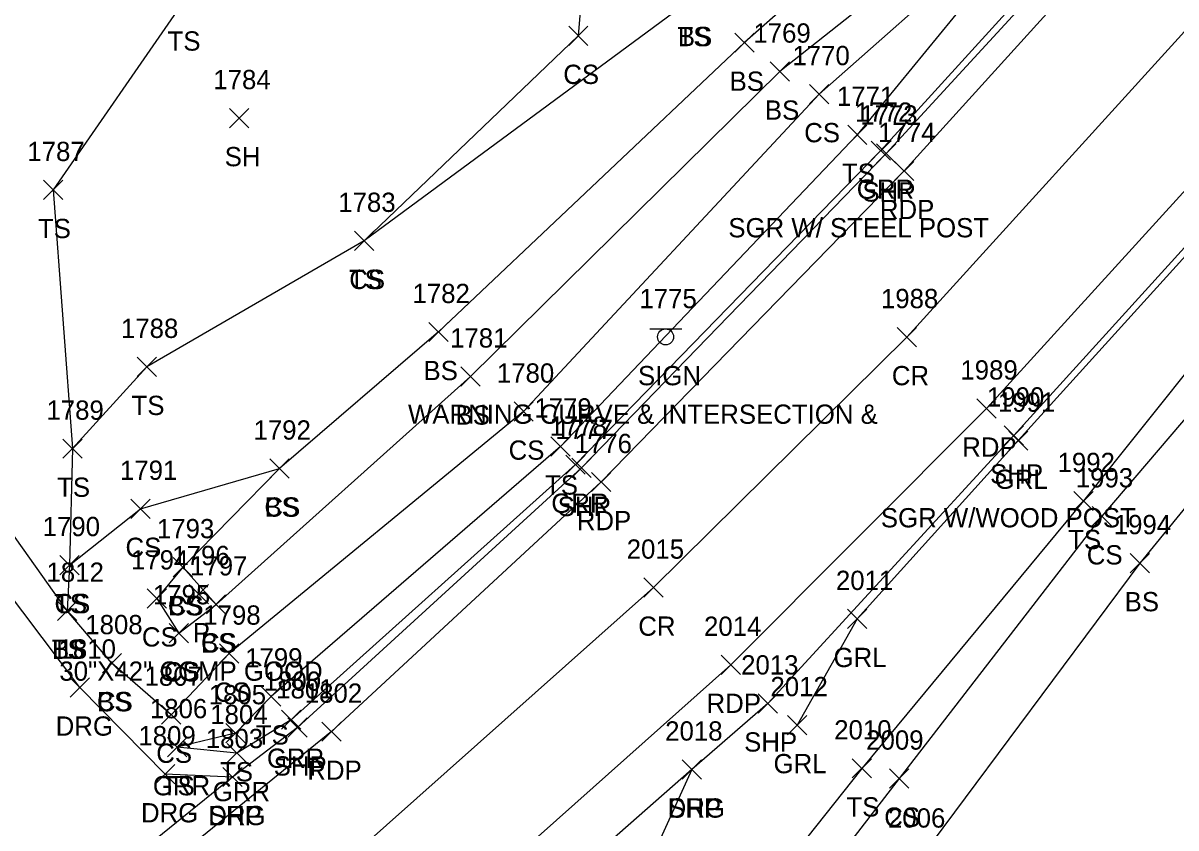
# Model space of a CAD drawing. Extents: x 1520648 to 1523413, y 732854 to 735518.
# Drawn here: x 1522132.5 to 1522252.1, y 733878.1 to 733961.6 of the extents above; entities that cross this region are included whole.
import ezdxf

# ---------------------------------------------------------------- set-up
doc = ezdxf.new("R2010")
doc.units = 0
for name, color, linetype in [('D_A', 7, 'Continuous'), ('D_C', 7, 'Continuous'), ('D_I', 7, 'Continuous'), ('D_TIC', 7, 'Continuous'), ('L_A', 7, 'Continuous'), ('L_I', 7, 'Continuous'), ('L_TIC', 7, 'Continuous'), ('LELB', 7, 'Continuous'), ('P_A', 7, 'Continuous'), ('P_I', 7, 'Continuous'), ('P_TIC', 7, 'Continuous'), ('PET', 7, 'Continuous'), ('PRC', 7, 'Continuous'), ('PSP', 7, 'Continuous'), ('R_A', 7, 'Continuous'), ('R_C', 7, 'Continuous'), ('R_I', 7, 'Continuous'), ('R_TIC', 7, 'Continuous'), ('RDG', 7, 'Continuous'), ('RGR', 7, 'Continuous'), ('S_A', 7, 'Continuous'), ('S_C', 7, 'Continuous'), ('S_I', 7, 'Continuous'), ('SSGN', 7, 'Continuous')]:
    doc.layers.add(name, color=color, linetype=linetype)

msp = doc.modelspace()

# ---------------------------------------------------------------- linework, layer by layer
at = {"layer": 'D_TIC'}
for points in [[(1522149.76, 733901.33), (1522151.76, 733903.33)], [(1522151.76, 733901.33), (1522149.76, 733903.33)]]:
    msp.add_lwpolyline(points, dxfattribs=at)
at = {"layer": 'L_TIC'}
for points in [[(1522189.12, 733959.27), (1522191.12, 733961.27)], [(1522191.12, 733959.27), (1522189.12, 733961.27)], [(1522206.37, 733958.56), (1522208.37, 733960.56)], [(1522208.37, 733958.56), (1522206.37, 733960.56)], [(1522206.37, 733958.56), (1522208.37, 733960.56)], [(1522208.37, 733958.56), (1522206.37, 733960.56)], [(1522210.03, 733955.56), (1522212.03, 733957.56)], [(1522212.03, 733955.56), (1522210.03, 733957.56)], [(1522214.11, 733953.22), (1522216.11, 733955.22)], [(1522216.11, 733953.22), (1522214.11, 733955.22)], [(1522153.95, 733950.73), (1522155.95, 733952.73)], [(1522155.95, 733950.73), (1522153.95, 733952.73)], [(1522218.06, 733949), (1522220.06, 733951)], [(1522220.06, 733949), (1522218.06, 733951)], [(1522134.66, 733943.27), (1522136.66, 733945.27)], [(1522136.66, 733943.27), (1522134.66, 733945.27)], [(1522166.92, 733937.99), (1522168.92, 733939.99)], [(1522168.92, 733937.99), (1522166.92, 733939.99)], [(1522166.92, 733937.99), (1522168.92, 733939.99)], [(1522168.92, 733937.99), (1522166.92, 733939.99)], [(1522174.61, 733928.53), (1522176.61, 733930.53)], [(1522176.61, 733928.53), (1522174.61, 733930.53)], [(1522144.37, 733924.91), (1522146.37, 733926.91)], [(1522146.37, 733924.91), (1522144.37, 733926.91)], [(1522177.95, 733923.91), (1522179.95, 733925.91)], [(1522179.95, 733923.91), (1522177.95, 733925.91)], [(1522183.45, 733920.27), (1522185.45, 733922.27)], [(1522185.45, 733920.27), (1522183.45, 733922.27)], [(1522136.65, 733916.42), (1522138.65, 733918.42)], [(1522138.65, 733916.42), (1522136.65, 733918.42)], [(1522136.65, 733916.42), (1522138.65, 733918.42)], [(1522138.65, 733916.42), (1522136.65, 733918.42)], [(1522187.26, 733916.65), (1522189.26, 733918.65)], [(1522189.26, 733916.65), (1522187.26, 733918.65)], [(1522158.12, 733914.36), (1522160.12, 733916.36)], [(1522160.12, 733914.36), (1522158.12, 733916.36)], [(1522158.12, 733914.36), (1522160.12, 733916.36)], [(1522160.12, 733914.36), (1522158.12, 733916.36)], [(1522143.71, 733910.18), (1522145.71, 733912.18)], [(1522145.71, 733910.18), (1522143.71, 733912.18)], [(1522241.52, 733910.99), (1522243.52, 733912.99)], [(1522243.52, 733910.99), (1522241.52, 733912.99)], [(1522243.42, 733909.4), (1522245.42, 733911.4)], [(1522245.42, 733909.4), (1522243.42, 733911.4)], [(1522136.34, 733904.34), (1522138.34, 733906.34)], [(1522138.34, 733904.34), (1522136.34, 733906.34)], [(1522136.34, 733904.34), (1522138.34, 733906.34)], [(1522138.34, 733904.34), (1522136.34, 733906.34)], [(1522148.1, 733904.12), (1522150.1, 733906.12)], [(1522150.1, 733904.12), (1522148.1, 733906.12)], [(1522148.1, 733904.12), (1522150.1, 733906.12)], [(1522150.1, 733904.12), (1522148.1, 733906.12)], [(1522247.35, 733904.54), (1522249.35, 733906.54)], [(1522249.35, 733904.54), (1522247.35, 733906.54)], [(1522145.41, 733900.88), (1522147.41, 733902.88)], [(1522147.41, 733900.88), (1522145.41, 733902.88)], [(1522136.09, 733899.6), (1522138.09, 733901.6)], [(1522138.09, 733899.6), (1522136.09, 733901.6)], [(1522136.09, 733899.6), (1522138.09, 733901.6)], [(1522138.09, 733899.6), (1522136.09, 733901.6)], [(1522151.54, 733900.26), (1522153.54, 733902.26)], [(1522153.54, 733900.26), (1522151.54, 733902.26)], [(1522151.54, 733900.26), (1522153.54, 733902.26)], [(1522153.54, 733900.26), (1522151.54, 733902.26)], [(1522151.54, 733900.26), (1522153.54, 733902.26)], [(1522153.54, 733900.26), (1522151.54, 733902.26)], [(1522147.69, 733897.26), (1522149.69, 733899.26)], [(1522149.69, 733897.26), (1522147.69, 733899.26)], [(1522152.91, 733895.15), (1522154.91, 733897.15)], [(1522154.91, 733895.15), (1522152.91, 733897.15)], [(1522140.75, 733894.16), (1522142.75, 733896.16)], [(1522142.75, 733894.16), (1522140.75, 733896.16)], [(1522140.75, 733894.16), (1522142.75, 733896.16)], [(1522142.75, 733894.16), (1522140.75, 733896.16)], [(1522157.26, 733890.71), (1522159.26, 733892.71)], [(1522159.26, 733890.71), (1522157.26, 733892.71)], [(1522146.9, 733888.81), (1522148.9, 733890.81)], [(1522148.9, 733888.81), (1522146.9, 733890.81)], [(1522153.55, 733886.89), (1522155.55, 733888.89)], [(1522155.55, 733886.89), (1522153.55, 733888.89)], [(1522147.5, 733885.44), (1522149.5, 733887.44)], [(1522149.5, 733885.44), (1522147.5, 733887.44)], [(1522218.52, 733883.24), (1522220.52, 733885.24)], [(1522220.52, 733883.24), (1522218.52, 733885.24)], [(1522222.41, 733882.18), (1522224.41, 733884.18)], [(1522224.41, 733882.18), (1522222.41, 733884.18)]]:
    msp.add_lwpolyline(points, dxfattribs=at)
at = {"layer": 'LELB'}
for points in [[(1522353.25, 734140.58), (1522319.92, 734106.37), (1522293, 734074.6), (1522275.62, 734051.29), (1522244.54, 734005.97), (1522222.7, 733979.34), (1522202, 733964.19), (1522167.92, 733938.99), (1522145.37, 733925.91), (1522137.65, 733917.42), (1522137.34, 733905.34), (1522137.09, 733900.6)], [(1522125.27, 734093.2), (1522135, 734067.14), (1522161.7, 734052.21), (1522168.2, 734018.04), (1522192.75, 733992.38), (1522190.12, 733960.27), (1522167.92, 733938.99)], [(1522105.42, 734074.14), (1522121.13, 734053.03), (1522134.54, 734027.27), (1522145.23, 734006.79), (1522143.45, 733990.96), (1522149.1, 733963.73), (1522135.66, 733944.27), (1522137.65, 733917.42)], [(1522234.99, 733978.89), (1522233.89, 733977.86), (1522225.33, 733975.44), (1522207.37, 733959.56)], [(1522239.33, 733974.37), (1522231.93, 733969.12), (1522215.11, 733954.22), (1522184.45, 733921.27), (1522153.91, 733896.15), (1522147.9, 733889.81), (1522141.75, 733895.16)], [(1522237.77, 733974.95), (1522230.05, 733971.66), (1522211.03, 733956.56), (1522178.95, 733924.91), (1522152.54, 733901.26)], [(1522241.57, 733972.22), (1522233.22, 733967.32), (1522219.06, 733950), (1522188.26, 733917.65), (1522158.26, 733891.71), (1522154.55, 733887.89), (1522148.5, 733886.44)], [(1522207.37, 733959.56), (1522175.61, 733929.53), (1522159.12, 733915.36), (1522149.1, 733905.12), (1522152.54, 733901.26)], [(1522141.75, 733895.16), (1522137.09, 733900.6), (1522127.81, 733913.65), (1522115.39, 733932.29), (1522101.35, 733953.08)], [(1522273.3, 733946.59), (1522271.43, 733944.22), (1522268.56, 733937.8), (1522262.2, 733922.49), (1522248.35, 733905.54), (1522225.71, 733875.09), (1522211.03, 733857.35), (1522192.48, 733835.82), (1522170.81, 733810.34), (1522151.93, 733786.41), (1522130.42, 733759.83), (1522111.64, 733741.03), (1522100.77, 733725.2)], [(1522266.63, 733945.22), (1522267.06, 733939.56), (1522257.32, 733925.54), (1522244.42, 733910.4), (1522223.41, 733883.18), (1522189.15, 733838.76), (1522168.77, 733813.86), (1522150.13, 733789.06), (1522128.4, 733762.92), (1522110.49, 733741.99), (1522098.34, 733726.66), (1522093.01, 733716.82)], [(1522270.74, 733944.98), (1522266.63, 733945.22), (1522254.91, 733927.51), (1522242.52, 733911.99), (1522219.52, 733884.24), (1522186.7, 733842.89), (1522166.07, 733817.07), (1522164.2, 733814.35), (1522137.24, 733813.36), (1522122.6, 733811.13)], [(1522137.34, 733905.34), (1522144.71, 733911.18), (1522159.12, 733915.36)], [(1522149.1, 733905.12), (1522146.41, 733901.88), (1522148.69, 733898.26), (1522152.54, 733901.26)]]:
    msp.add_lwpolyline(points, dxfattribs=at)
at = {"layer": 'P_TIC'}
for points in [[(1522221.05, 733947.06), (1522223.05, 733949.06)], [(1522223.05, 733947.06), (1522221.05, 733949.06)], [(1522222.91, 733945.24), (1522224.91, 733947.24)], [(1522224.91, 733945.24), (1522222.91, 733947.24)], [(1522223.2, 733928), (1522225.2, 733930)], [(1522225.2, 733928), (1522223.2, 733930)], [(1522231.46, 733920.59), (1522233.46, 733922.59)], [(1522233.46, 733920.59), (1522231.46, 733922.59)], [(1522234.29, 733917.79), (1522236.29, 733919.79)], [(1522236.29, 733917.79), (1522234.29, 733919.79)], [(1522189.45, 733914.42), (1522191.45, 733916.42)], [(1522191.45, 733914.42), (1522189.45, 733916.42)], [(1522191.48, 733912.96), (1522193.48, 733914.96)], [(1522193.48, 733912.96), (1522191.48, 733914.96)], [(1522196.91, 733902), (1522198.91, 733904)], [(1522198.91, 733902), (1522196.91, 733904)], [(1522204.93, 733893.99), (1522206.93, 733895.99)], [(1522206.93, 733893.99), (1522204.93, 733895.99)], [(1522208.78, 733889.98), (1522210.78, 733891.98)], [(1522210.78, 733889.98), (1522208.78, 733891.98)], [(1522159.99, 733887.49), (1522161.99, 733889.49)], [(1522161.99, 733887.49), (1522159.99, 733889.49)], [(1522163.52, 733887.05), (1522165.52, 733889.05)], [(1522165.52, 733887.05), (1522163.52, 733889.05)], [(1522200.9, 733883.12), (1522202.9, 733885.12)], [(1522202.9, 733883.12), (1522200.9, 733885.12)], [(1522153.25, 733882.34), (1522155.25, 733884.34)], [(1522155.25, 733882.34), (1522153.25, 733884.34)]]:
    msp.add_lwpolyline(points, dxfattribs=at)
at = {"layer": 'PET'}
for points in [[(1522409.89, 734185.46), (1522384.8, 734151.86), (1522362.15, 734120.96), (1522340.09, 734090.38), (1522317.27, 734060.02), (1522297.22, 734033.87), (1522262.69, 733990.17), (1522247.44, 733972.23), (1522223.91, 733946.24), (1522192.48, 733913.96), (1522164.52, 733888.05), (1522124.7, 733855.72), (1522089.98, 733831.33), (1522050.33, 733806.1), (1522008.23, 733782.16), (1521961.73, 733759.37), (1521937.85, 733748.92), (1521892.74, 733731.02), (1521853.04, 733716.93), (1521810.12, 733704.13), (1521784.9, 733696.8), (1521738.04, 733684.33), (1521683.5, 733669.74)], [(1522293.19, 733992.18), (1522263.71, 733955.95), (1522232.46, 733921.59), (1522205.93, 733894.99), (1522171.68, 733864.45), (1522150.76, 733846.95), (1522111.89, 733818.73), (1522077.26, 733795.56), (1522046.35, 733777.35), (1522014.71, 733760.04), (1521992.39, 733748.52), (1521963.75, 733735.05), (1521947.25, 733727.94), (1521903.49, 733710.07), (1521845.39, 733690.65), (1521824.85, 733681.25), (1521803.81, 733674.87), (1521790.98, 733674.84), (1521764.05, 733667.92), (1521729.46, 733658.42), (1521691.16, 733648.14)]]:
    msp.add_lwpolyline(points, dxfattribs=at)
at = {"layer": 'PRC'}
msp.add_lwpolyline([(1522254.71, 733962.62), (1522224.2, 733929), (1522197.91, 733903), (1522164.25, 733873.02), (1522142.54, 733855.17), (1522104.41, 733827.43), (1522070.85, 733804.7), (1522039.57, 733786.25), (1522009.6, 733770.04), (1521986.99, 733758.56), (1521958.12, 733745.43), (1521942.23, 733738.37), (1521896.32, 733720.33), (1521857.71, 733706.32), (1521841.62, 733701.43), (1521812.17, 733692.84), (1521787.03, 733685.66), (1521768.25, 733680.62), (1521726.09, 733669.37), (1521688.17, 733658.56)], dxfattribs=at)
at = {"layer": 'PSP'}
for points in [[(1522407.44, 734186.96), (1522382.7, 734153.4), (1522359.98, 734122.45), (1522337.92, 734092.02), (1522315.01, 734061.41), (1522295.21, 734035.76), (1522260.62, 733991.79), (1522245.88, 733973.99), (1522222.05, 733948.06), (1522190.45, 733915.42), (1522160.99, 733888.49), (1522154.25, 733883.34), (1522127.34, 733861.55), (1522088.3, 733833.58), (1522048.98, 733808.78), (1522007.27, 733785.06), (1521960.9, 733762.47), (1521936.68, 733751.08), (1521891.96, 733733.48), (1521851.86, 733719.56), (1521809.02, 733706.62), (1521784.1, 733699.99), (1521736.06, 733688.52), (1521682.58, 733672.91)], [(1522408.2, 734139.28), (1522381.04, 734102.47), (1522353.02, 734064.87), (1522324.01, 734025.28), (1522296.17, 733989.55), (1522266.63, 733953.31), (1522235.29, 733918.79), (1522209.78, 733890.98), (1522201.9, 733884.12), (1522173.49, 733859.11), (1522154.03, 733843.41), (1522113.55, 733816.07), (1522079.34, 733793.19), (1522048.3, 733774.46), (1522016.59, 733757.42), (1521993.94, 733745.83), (1521965.16, 733732.44), (1521948.66, 733724.97), (1521904.28, 733707.61), (1521888.63, 733701.99), (1521847.29, 733686.72), (1521809.29, 733673.67)]]:
    msp.add_lwpolyline(points, dxfattribs=at)
at = {"layer": 'R_TIC'}
for points in [[(1522220.51, 733947.35), (1522222.51, 733949.35)], [(1522222.51, 733947.35), (1522220.51, 733949.35)], [(1522234.76, 733917.25), (1522236.76, 733919.25)], [(1522236.76, 733917.25), (1522234.76, 733919.25)], [(1522188.83, 733914.76), (1522190.83, 733916.76)], [(1522190.83, 733914.76), (1522188.83, 733916.76)], [(1522218.05, 733898.75), (1522220.05, 733900.75)], [(1522220.05, 733898.75), (1522218.05, 733900.75)], [(1522137.42, 733891.63), (1522139.42, 733893.63)], [(1522139.42, 733891.63), (1522137.42, 733893.63)], [(1522159.34, 733888.29), (1522161.34, 733890.29)], [(1522161.34, 733888.29), (1522159.34, 733890.29)], [(1522211.83, 733887.73), (1522213.83, 733889.73)], [(1522213.83, 733887.73), (1522211.83, 733889.73)], [(1522147.5, 733885.44), (1522149.5, 733887.44)], [(1522149.5, 733885.44), (1522147.5, 733887.44)], [(1522153.71, 733884.83), (1522155.71, 733886.83)], [(1522155.71, 733884.83), (1522153.71, 733886.83)], [(1522146.27, 733882.63), (1522148.27, 733884.63)], [(1522148.27, 733882.63), (1522146.27, 733884.63)], [(1522200.9, 733883.12), (1522202.9, 733885.12)], [(1522202.9, 733883.12), (1522200.9, 733885.12)], [(1522153.25, 733882.34), (1522155.25, 733884.34)], [(1522155.25, 733882.34), (1522153.25, 733884.34)]]:
    msp.add_lwpolyline(points, dxfattribs=at)
at = {"layer": 'RDG'}
for points in [[(1522154.25, 733883.34), (1522147.27, 733883.63), (1522138.42, 733892.63), (1522124.65, 733910.85), (1522111.52, 733931.27), (1522101.35, 733953.08), (1522088.31, 733979.36), (1522086.25, 733984.71)], [(1522201.9, 733884.12), (1522195.75, 733870.56), (1522182.51, 733850.34), (1522162.18, 733834.79), (1522133.75, 733820.11), (1522113.55, 733816.07)]]:
    msp.add_lwpolyline(points, dxfattribs=at)
at = {"layer": 'RGR'}
for points in [[(1522309.58, 734064.85), (1522305.06, 734052.2), (1522294.68, 734036.56), (1522260.13, 733992.38), (1522248.03, 733977.91), (1522242.5, 733971.47), (1522221.51, 733948.35), (1522189.83, 733915.76), (1522160.34, 733889.29), (1522154.71, 733885.83), (1522148.5, 733886.44)], [(1522327.77, 734020.69), (1522316.41, 734013), (1522308.3, 734003.69), (1522296.64, 733988.96), (1522267.17, 733952.95), (1522235.76, 733918.25), (1522219.05, 733899.75), (1522212.83, 733888.73)]]:
    msp.add_lwpolyline(points, dxfattribs=at)
at = {"layer": 'SSGN'}
for p, q in [((1522197.53, 733929.86), (1522200.86, 733929.86)), ((1522199.17, 733929.02), (1522199.17, 733929.02))]:
    msp.add_line(p, q, dxfattribs=at)
msp.add_circle((1522199.17, 733929.02), 0.833, dxfattribs=at)

# ---------------------------------------------------------------- texts
at = {"layer": 'D_A'}
msp.add_text('P', height=2, dxfattribs=at).set_placement((1522150.13, 733897.33))
at = {"layer": 'D_C'}
msp.add_text('30"X42" CGMP GOOD', height=2, dxfattribs=at).set_placement((1522136.29, 733893.33))
at = {"layer": 'D_I'}
msp.add_text('1796', height=2, dxfattribs=at).set_placement((1522148.01, 733905.33))
at = {"layer": 'L_A'}
for s, p in [('TS', (1522200.41, 733959.19)), ('TS', (1522200.41, 733959.19)), ('BS', (1522200.44, 733959.19)), ('TS', (1522147.51, 733958.73)), ('CS', (1522188.56, 733955.27)), ('BS', (1522205.81, 733954.56)), ('BS', (1522205.81, 733954.56)), ('BS', (1522209.47, 733951.56)), ('CS', (1522213.55, 733949.22)), ('SH', (1522153.44, 733946.73)), ('TS', (1522217.47, 733945)), ('TS', (1522134.07, 733939.27)), ('TS', (1522166.33, 733933.99)), ('CS', (1522166.36, 733933.99)), ('BS', (1522174.06, 733924.53)), ('TS', (1522143.78, 733920.91)), ('BS', (1522177.39, 733919.91)), ('CS', (1522182.89, 733916.27)), ('TS', (1522136.06, 733912.42)), ('TS', (1522136.06, 733912.42)), ('TS', (1522186.67, 733912.65)), ('CS', (1522157.56, 733910.36)), ('BS', (1522157.56, 733910.36)), ('TS', (1522240.93, 733906.99)), ('CS', (1522143.15, 733906.18)), ('CS', (1522242.86, 733905.4)), ('BS', (1522246.79, 733900.54)), ('TS', (1522135.75, 733900.34)), ('CS', (1522135.78, 733900.34)), ('CS', (1522147.54, 733900.12)), ('BS', (1522147.54, 733900.12)), ('CS', (1522144.85, 733896.88)), ('CS', (1522150.98, 733896.26)), ('BS', (1522150.98, 733896.26)), ('BS', (1522150.98, 733896.26)), ('TS', (1522135.5, 733895.6)), ('BS', (1522135.53, 733895.6)), ('CS', (1522147.13, 733893.26)), ('CS', (1522152.35, 733891.15)), ('CS', (1522140.19, 733890.16)), ('BS', (1522140.19, 733890.16)), ('TS', (1522156.67, 733886.71)), ('CS', (1522146.34, 733884.81)), ('TS', (1522152.96, 733882.89)), ('TS', (1522146.91, 733881.44)), ('TS', (1522217.93, 733879.24)), ('CS', (1522221.85, 733878.18))]:
    msp.add_text(s, height=2, dxfattribs=at).set_placement(p)
at = {"layer": 'L_I'}
for s, p in [('1769', (1522208.28, 733959.56)), ('1770', (1522212.33, 733957.22)), ('1784', (1522152.26, 733954.73)), ('1771', (1522216.94, 733953)), ('1787', (1522132.97, 733947.27)), ('1783', (1522165.22, 733941.99)), ('1783', (1522165.22, 733941.99)), ('1782', (1522172.92, 733932.53)), ('1788', (1522142.68, 733928.91)), ('1781', (1522176.82, 733927.91)), ('1780', (1522181.67, 733924.27)), ('1789', (1522134.95, 733920.42)), ('1789', (1522134.95, 733920.42)), ('1779', (1522185.56, 733920.65)), ('1792', (1522156.43, 733918.36)), ('1792', (1522156.43, 733918.36)), ('1992', (1522239.83, 733914.99)), ('1791', (1522142.58, 733914.18)), ('1993', (1522241.72, 733913.4)), ('1790', (1522134.56, 733908.34)), ('1790', (1522134.56, 733908.34)), ('1793', (1522146.41, 733908.12)), ('1793', (1522146.41, 733908.12)), ('1994', (1522245.66, 733908.54)), ('1794', (1522143.72, 733904.88)), ('1797', (1522149.85, 733904.26)), ('1797', (1522149.85, 733904.26)), ('1797', (1522149.85, 733904.26)), ('1812', (1522134.96, 733903.6)), ('1812', (1522134.96, 733903.6)), ('1795', (1522145.99, 733901.26)), ('1808', (1522138.98, 733898.16)), ('1808', (1522138.98, 733898.16)), ('1798', (1522151.22, 733899.15)), ('1799', (1522155.56, 733894.71)), ('1807', (1522145.13, 733892.81)), ('1805', (1522151.78, 733890.89)), ('1806', (1522145.68, 733889.44)), ('2010', (1522216.66, 733887.24)), ('2009', (1522219.98, 733886.18)), ('2006', (1522222.24, 733878.09)), ('2006', (1522222.24, 733878.09))]:
    msp.add_text(s, height=2, dxfattribs=at).set_placement(p)
at = {"layer": 'P_A'}
for s, p in [('SHP', (1522219.59, 733943.06)), ('RDP', (1522221.4, 733941.24)), ('CR', (1522222.64, 733924)), ('RDP', (1522229.94, 733916.59)), ('SHP', (1522232.83, 733913.79)), ('SHP', (1522187.98, 733910.42)), ('RDP', (1522189.96, 733908.96)), ('CR', (1522196.34, 733898)), ('RDP', (1522203.42, 733889.99)), ('SHP', (1522207.32, 733885.98)), ('SHP', (1522158.52, 733883.49)), ('RDP', (1522162.01, 733883.05)), ('SHP', (1522199.44, 733879.12)), ('SHP', (1522151.79, 733878.34))]:
    msp.add_text(s, height=2, dxfattribs=at).set_placement(p)
at = {"layer": 'P_I'}
for s, p in [('1773', (1522219.36, 733951.06)), ('1774', (1522221.22, 733949.24)), ('1988', (1522221.51, 733932)), ('1989', (1522229.75, 733924.59)), ('1990', (1522232.51, 733921.79)), ('1777', (1522187.75, 733918.42)), ('1776', (1522189.73, 733916.96)), ('2015', (1522195.14, 733906)), ('2014', (1522203.16, 733897.99)), ('2013', (1522207.01, 733893.98)), ('1801', (1522158.78, 733891.49)), ('1802', (1522161.75, 733891.05)), ('1803', (1522151.48, 733886.34)), ('2018', (1522199.13, 733887.12))]:
    msp.add_text(s, height=2, dxfattribs=at).set_placement(p)
at = {"layer": 'R_A'}
for s, p in [('GRR', (1522219, 733943.35)), ('GRL', (1522233.31, 733913.25)), ('GRR', (1522187.32, 733910.76)), ('GRL', (1522216.59, 733894.75)), ('DRG', (1522135.91, 733887.63)), ('GRR', (1522157.82, 733884.29)), ('GRL', (1522210.37, 733883.73)), ('GRR', (1522145.99, 733881.44)), ('GRR', (1522152.2, 733880.83)), ('DRG', (1522199.39, 733879.12)), ('DRG', (1522144.76, 733878.63)), ('DRG', (1522151.74, 733878.34))]:
    msp.add_text(s, height=2, dxfattribs=at).set_placement(p)
at = {"layer": 'R_C'}
for s, p in [('SGR W/ STEEL POST', (1522205.68, 733939.35)), ('SGR W/WOOD POST', (1522221.5, 733909.25))]:
    msp.add_text(s, height=2, dxfattribs=at).set_placement(p)
at = {"layer": 'R_I'}
for s, p in [('1772', (1522218.82, 733951.35)), ('1991', (1522233.64, 733921.25)), ('1778', (1522187.14, 733918.76)), ('2011', (1522216.84, 733902.75)), ('1810', (1522136.21, 733895.63)), ('1800', (1522157.48, 733892.29)), ('2012', (1522210.05, 733891.73)), ('1806', (1522145.68, 733889.44)), ('1804', (1522151.94, 733888.83)), ('1809', (1522144.49, 733886.63)), ('1803', (1522151.48, 733886.34)), ('2018', (1522199.13, 733887.12))]:
    msp.add_text(s, height=2, dxfattribs=at).set_placement(p)
at = {"layer": 'S_A'}
msp.add_text('SIGN', height=2, dxfattribs=at).set_placement((1522196.31, 733924))
at = {"layer": 'S_C'}
msp.add_text('WARNING CURVE & INTERSECTION &', height=2, dxfattribs=at).set_placement((1522172.45, 733920))
at = {"layer": 'S_I'}
msp.add_text('1775', height=2, dxfattribs=at).set_placement((1522196.46, 733932))

doc.saveas('drawing.dxf')
